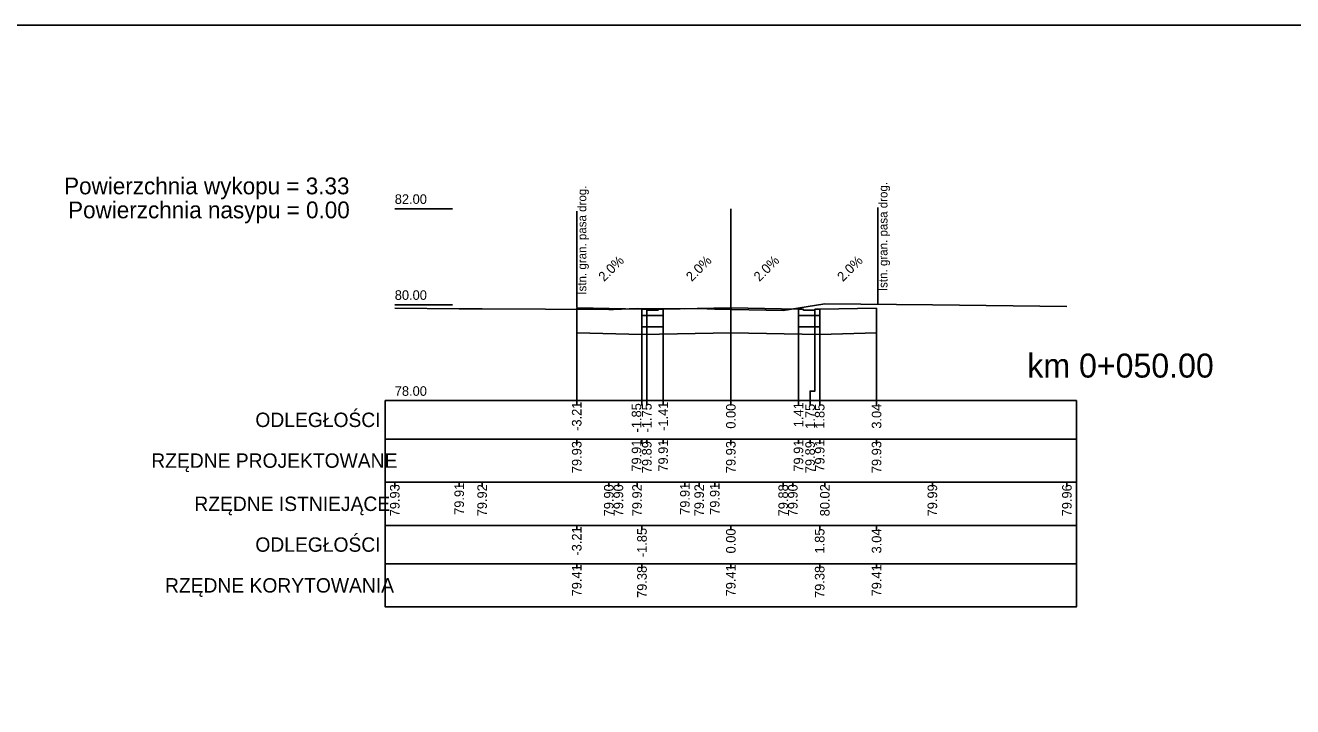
# Model space of a CAD drawing. Extents: x 7492871 to 7493499, y 5802964 to 5802992.
# Drawn here: x 7492903.18 to 7492929.58, y 5802978.08 to 5802992.28 of the extents above; entities that cross this region are included whole.
import ezdxf

# ---------------------------------------------------------------- set-up
doc = ezdxf.new("R2010")
doc.units = 0
for name, color, linetype in [('_wydruk', 7, 'Continuous'), ('d_pop_nasyp_opis', 7, 'Continuous'), ('d_pop_wykop_opis', 7, 'Continuous'), ('opisy_ramki_pop', 7, 'Continuous'), ('pop_comp_kostka', 7, 'Continuous'), ('pop_comp_lawa', 7, 'Continuous'), ('pop_comp_scieralna', 7, 'Continuous'), ('pop_granica_istn', 7, 'Continuous'), ('pop_opis', 7, 'Continuous'), ('pop_os', 7, 'Continuous'), ('pop_pikietaz', 7, 'Continuous'), ('pop_teren', 7, 'Continuous')]:
    doc.layers.add(name, color=color, linetype=linetype)

msp = doc.modelspace()

# ---------------------------------------------------------------- linework, layer by layer
msp.add_lwpolyline([(7492914.664, 5802986.392), (7492916.023, 5802986.365), (7492916.123, 5802986.365), (7492916.124, 5802986.345), (7492916.363, 5802986.345), (7492916.364, 5802986.365), (7492916.464, 5802986.365), (7492917.874, 5802986.393), (7492919.284, 5802986.365), (7492919.384, 5802986.365), (7492919.385, 5802986.345), (7492919.624, 5802986.345), (7492919.625, 5802986.365), (7492919.725, 5802986.365), (7492920.91, 5802986.389)])
at = {"layer": '_wydruk'}
msp.add_lwpolyline([(7492871.369, 5802992.281), (7493499.283, 5802992.281), (7493499.283, 5802963.881), (7492871.369, 5802963.881)], close=True, dxfattribs=at)
at = {"layer": 'opisy_ramki_pop'}
for points in [[(7492914.664, 5802985.872), (7492914.664, 5802984.659), (7492914.664, 5802984.659), (7492914.664, 5802984.459)], [(7492916.023, 5802985.836), (7492916.023, 5802984.659), (7492916.023, 5802984.659), (7492916.023, 5802984.459)], [(7492917.874, 5802985.873), (7492917.874, 5802984.659), (7492917.874, 5802984.659), (7492917.874, 5802984.459)], [(7492919.725, 5802985.836), (7492919.725, 5802984.659), (7492919.725, 5802984.659), (7492919.725, 5802984.459)], [(7492920.91, 5802985.869), (7492920.91, 5802984.659), (7492920.91, 5802984.659), (7492920.91, 5802984.459)]]:
    msp.add_lwpolyline(points, dxfattribs=at)
at = {"layer": 'pop_comp_kostka'}
for p, q in [((7492916.123, 5802986.365), (7492916.023, 5802986.365)), ((7492916.023, 5802986.365), (7492916.023, 5802986.235)), ((7492916.124, 5802986.345), (7492916.123, 5802986.365)), ((7492916.363, 5802986.345), (7492916.124, 5802986.345)), ((7492916.364, 5802986.365), (7492916.363, 5802986.345)), ((7492916.464, 5802986.365), (7492916.364, 5802986.365)), ((7492916.464, 5802986.235), (7492916.464, 5802986.365)), ((7492919.384, 5802986.365), (7492919.284, 5802986.365)), ((7492919.284, 5802986.365), (7492919.284, 5802986.235)), ((7492919.385, 5802986.345), (7492919.384, 5802986.365)), ((7492919.624, 5802986.345), (7492919.385, 5802986.345)), ((7492919.625, 5802986.365), (7492919.624, 5802986.345)), ((7492919.725, 5802986.365), (7492919.625, 5802986.365)), ((7492919.725, 5802986.235), (7492919.725, 5802986.365)), ((7492916.023, 5802986.235), (7492916.464, 5802986.235)), ((7492919.284, 5802986.235), (7492919.725, 5802986.235))]:
    msp.add_line(p, q, dxfattribs=at)
at = {"layer": 'pop_comp_lawa'}
for p, q in [((7492916.464, 5802986.235), (7492916.023, 5802986.235)), ((7492916.023, 5802986.235), (7492916.023, 5802985.995)), ((7492916.464, 5802985.995), (7492916.464, 5802986.235)), ((7492919.725, 5802986.235), (7492919.284, 5802986.235)), ((7492919.284, 5802986.235), (7492919.284, 5802985.995)), ((7492919.725, 5802985.995), (7492919.725, 5802986.235)), ((7492916.023, 5802985.995), (7492916.464, 5802985.995)), ((7492919.284, 5802985.995), (7492919.725, 5802985.995))]:
    msp.add_line(p, q, dxfattribs=at)
at = {"layer": 'pop_comp_scieralna'}
for p, q in [((7492916.023, 5802986.365), (7492914.664, 5802986.392)), ((7492914.664, 5802986.392), (7492914.664, 5802985.872)), ((7492916.023, 5802985.995), (7492916.023, 5802986.365)), ((7492917.874, 5802986.393), (7492916.464, 5802986.365)), ((7492916.464, 5802986.365), (7492916.464, 5802985.995)), ((7492917.874, 5802985.873), (7492917.874, 5802986.393)), ((7492919.284, 5802986.365), (7492917.874, 5802986.393)), ((7492917.874, 5802986.393), (7492917.874, 5802985.873)), ((7492919.284, 5802985.995), (7492919.284, 5802986.365)), ((7492920.91, 5802986.389), (7492919.725, 5802986.365)), ((7492919.725, 5802986.365), (7492919.725, 5802985.995)), ((7492920.91, 5802985.869), (7492920.91, 5802986.389)), ((7492914.664, 5802985.872), (7492916.023, 5802985.836)), ((7492916.464, 5802985.995), (7492916.023, 5802985.995)), ((7492916.023, 5802985.836), (7492917.874, 5802985.873)), ((7492917.874, 5802985.873), (7492919.725, 5802985.836)), ((7492919.725, 5802985.995), (7492919.284, 5802985.995)), ((7492919.725, 5802985.836), (7492920.91, 5802985.869))]:
    msp.add_line(p, q, dxfattribs=at)
at = {"layer": 'pop_granica_istn'}
for p, q in [((7492914.664, 5802986.905), (7492914.664, 5802988.405)), ((7492920.939, 5802986.981), (7492920.939, 5802988.481)), ((7492914.664, 5802986.405), (7492914.664, 5802986.905)), ((7492920.939, 5802986.481), (7492920.939, 5802986.981))]:
    msp.add_line(p, q, dxfattribs=at)
at = {"layer": 'pop_opis'}
for p, q in [((7492910.874, 5802988.459), (7492912.074, 5802988.459)), ((7492910.874, 5802986.459), (7492912.074, 5802986.459)), ((7492910.674, 5802984.459), (7492910.674, 5802982.759)), ((7492910.674, 5802984.459), (7492910.674, 5802982.759)), ((7492910.674, 5802984.459), (7492910.674, 5802982.759)), ((7492910.674, 5802984.459), (7492910.674, 5802982.759)), ((7492910.874, 5802984.459), (7492912.074, 5802984.459)), ((7492914.664, 5802984.359), (7492914.664, 5802984.459)), ((7492916.023, 5802984.359), (7492916.023, 5802984.459)), ((7492916.124, 5802984.359), (7492916.124, 5802984.459)), ((7492916.464, 5802984.359), (7492916.464, 5802984.459)), ((7492917.874, 5802984.359), (7492917.874, 5802984.459)), ((7492919.284, 5802984.359), (7492919.284, 5802984.459)), ((7492919.525, 5802984.359), (7492919.525, 5802984.459)), ((7492919.725, 5802984.359), (7492919.725, 5802984.459)), ((7492920.91, 5802984.359), (7492920.91, 5802984.459)), ((7492910.674, 5802983.659), (7492925.074, 5802983.659)), ((7492910.674, 5802983.659), (7492925.074, 5802983.659)), ((7492910.674, 5802983.659), (7492925.074, 5802983.659)), ((7492910.674, 5802983.659), (7492925.074, 5802983.659)), ((7492914.664, 5802983.559), (7492914.664, 5802983.659)), ((7492916.023, 5802983.559), (7492916.023, 5802983.659)), ((7492916.124, 5802983.559), (7492916.124, 5802983.659)), ((7492916.464, 5802983.559), (7492916.464, 5802983.659)), ((7492917.874, 5802983.559), (7492917.874, 5802983.659)), ((7492919.284, 5802983.559), (7492919.284, 5802983.659)), ((7492919.525, 5802983.559), (7492919.525, 5802983.659)), ((7492919.725, 5802983.559), (7492919.725, 5802983.659)), ((7492920.91, 5802983.559), (7492920.91, 5802983.659)), ((7492910.674, 5802982.759), (7492910.674, 5802981.859)), ((7492910.874, 5802982.659), (7492910.874, 5802982.759)), ((7492912.216, 5802982.659), (7492912.216, 5802982.759)), ((7492912.693, 5802982.659), (7492912.693, 5802982.759)), ((7492915.332, 5802982.659), (7492915.332, 5802982.759)), ((7492915.532, 5802982.659), (7492915.532, 5802982.759)), ((7492915.92, 5802982.659), (7492915.92, 5802982.759)), ((7492916.917, 5802982.659), (7492916.917, 5802982.759)), ((7492917.215, 5802982.659), (7492917.215, 5802982.759)), ((7492917.539, 5802982.659), (7492917.539, 5802982.759)), ((7492918.965, 5802982.659), (7492918.965, 5802982.759)), ((7492919.165, 5802982.659), (7492919.165, 5802982.759)), ((7492919.832, 5802982.659), (7492919.832, 5802982.759)), ((7492922.072, 5802982.659), (7492922.072, 5802982.759)), ((7492924.874, 5802982.659), (7492924.874, 5802982.759)), ((7492910.674, 5802981.859), (7492910.674, 5802980.159)), ((7492914.664, 5802981.759), (7492914.664, 5802981.859)), ((7492916.023, 5802981.759), (7492916.023, 5802981.859)), ((7492917.874, 5802981.759), (7492917.874, 5802981.859)), ((7492919.725, 5802981.759), (7492919.725, 5802981.859)), ((7492920.91, 5802981.759), (7492920.91, 5802981.859)), ((7492910.674, 5802981.059), (7492925.074, 5802981.059)), ((7492914.664, 5802980.959), (7492914.664, 5802981.059)), ((7492916.023, 5802980.959), (7492916.023, 5802981.059)), ((7492917.874, 5802980.959), (7492917.874, 5802981.059)), ((7492919.725, 5802980.959), (7492919.725, 5802981.059)), ((7492920.91, 5802980.959), (7492920.91, 5802981.059))]:
    msp.add_line(p, q, dxfattribs=at)
for points in [[(7492914.664, 5802986.392), (7492914.664, 5802984.659), (7492914.664, 5802984.659), (7492914.664, 5802984.459)], [(7492916.023, 5802986.365), (7492916.023, 5802984.659), (7492916.023, 5802984.659), (7492916.023, 5802984.459)], [(7492916.124, 5802986.345), (7492916.124, 5802984.659), (7492916.124, 5802984.659), (7492916.124, 5802984.459)], [(7492916.464, 5802986.365), (7492916.464, 5802984.659), (7492916.464, 5802984.659), (7492916.464, 5802984.459)], [(7492917.874, 5802986.393), (7492917.874, 5802984.659), (7492917.874, 5802984.659), (7492917.874, 5802984.459)], [(7492919.284, 5802986.365), (7492919.284, 5802984.659), (7492919.284, 5802984.659), (7492919.284, 5802984.459)], [(7492919.624, 5802986.345), (7492919.624, 5802984.659), (7492919.525, 5802984.659), (7492919.525, 5802984.459)], [(7492919.725, 5802986.365), (7492919.725, 5802984.659), (7492919.725, 5802984.659), (7492919.725, 5802984.459)], [(7492920.91, 5802986.389), (7492920.91, 5802984.659), (7492920.91, 5802984.659), (7492920.91, 5802984.459)]]:
    msp.add_lwpolyline(points, dxfattribs=at)
for points in [[(7492910.674, 5802984.459), (7492910.674, 5802982.759), (7492925.074, 5802982.759), (7492925.074, 5802984.459)], [(7492910.674, 5802984.459), (7492910.674, 5802982.759), (7492925.074, 5802982.759), (7492925.074, 5802984.459)], [(7492910.674, 5802984.459), (7492910.674, 5802982.759), (7492925.074, 5802982.759), (7492925.074, 5802984.459)], [(7492910.674, 5802984.459), (7492910.674, 5802982.759), (7492925.074, 5802982.759), (7492925.074, 5802984.459)], [(7492910.674, 5802982.759), (7492910.674, 5802981.859), (7492925.074, 5802981.859), (7492925.074, 5802982.759)], [(7492910.674, 5802981.859), (7492910.674, 5802980.159), (7492925.074, 5802980.159), (7492925.074, 5802981.859)]]:
    msp.add_lwpolyline(points, close=True, dxfattribs=at)
at = {"layer": 'pop_os'}
msp.add_line((7492917.874, 5802988.459), (7492917.874, 5802984.459), dxfattribs=at)
at = {"layer": 'pop_teren'}
msp.add_lwpolyline([(7492910.874, 5802986.388), (7492912.216, 5802986.372), (7492912.693, 5802986.375), (7492915.332, 5802986.356), (7492915.432, 5802986.357), (7492915.92, 5802986.381), (7492916.917, 5802986.372), (7492917.215, 5802986.379), (7492917.539, 5802986.367), (7492918.965, 5802986.336), (7492919.093, 5802986.356), (7492919.832, 5802986.475), (7492922.072, 5802986.454), (7492924.874, 5802986.424)], dxfattribs=at)

# ---------------------------------------------------------------- texts
at = {"layer": 'd_pop_nasyp_opis'}
msp.add_text('Powierzchnia nasypu = 0.00', height=0.35, dxfattribs=at).set_placement((7492904.069, 5802988.259))
at = {"layer": 'd_pop_wykop_opis'}
msp.add_text('Powierzchnia wykopu = 3.33', height=0.35, dxfattribs=at).set_placement((7492903.986, 5802988.759))
at = {"layer": 'pop_granica_istn'}
for p in [(7492921.137, 5802986.742), (7492914.863, 5802986.667)]:
    msp.add_text('Istn. gran. pasa drog.', height=0.18, rotation=90, dxfattribs=at).set_placement(p)
at = {"layer": 'pop_opis'}
for s, height, p in [('82.00', 0.2, (7492910.874, 5802988.559)), ('80.00', 0.2, (7492910.874, 5802986.559)), ('78.00', 0.2, (7492910.874, 5802984.559)), ('ODLEGŁOŚCI', 0.3, (7492907.97, 5802983.909)), ('ODLEGŁOŚCI', 0.3, (7492907.97, 5802983.909)), ('ODLEGŁOŚCI', 0.3, (7492907.97, 5802983.909)), ('ODLEGŁOŚCI', 0.3, (7492907.97, 5802983.909)), ('RZĘDNE PROJEKTOWANE', 0.3, (7492905.802, 5802983.059)), ('RZĘDNE PROJEKTOWANE', 0.3, (7492905.802, 5802983.059)), ('RZĘDNE PROJEKTOWANE', 0.3, (7492905.802, 5802983.059)), ('RZĘDNE PROJEKTOWANE', 0.3, (7492905.802, 5802983.059)), ('RZĘDNE ISTNIEJĄCE', 0.3, (7492906.699, 5802982.159)), ('ODLEGŁOŚCI', 0.3, (7492907.97, 5802981.309)), ('RZĘDNE KORYTOWANIA', 0.3, (7492906.088, 5802980.459))]:
    msp.add_text(s, height=height, dxfattribs=at).set_placement(p)
for s, rotation, p in [('2.0%', 45, (7492915.235, 5802986.929)), ('2.0%', 45, (7492917.06, 5802986.929)), ('2.0%', 45, (7492918.47, 5802986.929)), ('2.0%', 45, (7492920.209, 5802986.927)), ('-3.21', 90, (7492914.764, 5802983.829)), ('-1.85', 90, (7492916.01, 5802983.796)), ('-1.75', 90, (7492916.224, 5802983.796)), ('-1.41', 90, (7492916.564, 5802983.829)), ('0.00', 90, (7492917.974, 5802983.874)), ('1.41', 90, (7492919.384, 5802983.905)), ('1.75', 90, (7492919.625, 5802983.873)), ('1.85', 90, (7492919.825, 5802983.873)), ('3.04', 90, (7492921.01, 5802983.874)), ('79.93', 90, (7492914.764, 5802982.947)), ('79.91', 90, (7492916.01, 5802982.978)), ('79.89', 90, (7492916.224, 5802982.946)), ('79.91', 90, (7492916.564, 5802982.978)), ('79.93', 90, (7492917.974, 5802982.947)), ('79.91', 90, (7492919.384, 5802982.978)), ('79.89', 90, (7492919.625, 5802982.946)), ('79.91', 90, (7492919.825, 5802982.978)), ('79.93', 90, (7492921.01, 5802982.947)), ('79.93', 90, (7492910.974, 5802982.047)), ('79.91', 90, (7492912.316, 5802982.078)), ('79.92', 90, (7492912.793, 5802982.048)), ('79.90', 90, (7492915.432, 5802982.047)), ('79.90', 90, (7492915.632, 5802982.047)), ('79.92', 90, (7492916.02, 5802982.048)), ('79.91', 90, (7492917.017, 5802982.078)), ('79.92', 90, (7492917.315, 5802982.048)), ('79.91', 90, (7492917.639, 5802982.078)), ('79.88', 90, (7492919.065, 5802982.046)), ('79.90', 90, (7492919.265, 5802982.047)), ('80.02', 90, (7492919.932, 5802982.048)), ('79.99', 90, (7492922.172, 5802982.046)), ('79.96', 90, (7492924.974, 5802982.047)), ('-3.21', 90, (7492914.764, 5802981.229)), ('-1.85', 90, (7492916.123, 5802981.196)), ('0.00', 90, (7492917.974, 5802981.274)), ('1.85', 90, (7492919.825, 5802981.273)), ('3.04', 90, (7492921.01, 5802981.274)), ('79.41', 90, (7492914.764, 5802980.378)), ('79.38', 90, (7492916.123, 5802980.346)), ('79.41', 90, (7492917.974, 5802980.378)), ('79.38', 90, (7492919.825, 5802980.346)), ('79.41', 90, (7492921.01, 5802980.378))]:
    msp.add_text(s, height=0.2, rotation=rotation, dxfattribs=at).set_placement(p)
at = {"layer": 'pop_pikietaz'}
msp.add_text('km 0+050.00', height=0.5, dxfattribs=at).set_placement((7492924.05, 5802984.939))

doc.saveas('drawing.dxf')
